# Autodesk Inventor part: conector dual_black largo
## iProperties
Created: 2008-01
Part Number: conector dual_black largo
Document SubType Name: Modeling
Designer: eruiz-tagle
Mass: 0.0867993 g
Surface Area: 6.41708 cm^2
Volume: 0.0867993 cm^3
Density: 1 g/cm^3
Author: eruiz-tagle
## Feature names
1. Extrusion1
2. Shell1
3. Revolution1
4. Extrusion2
5. Fillet1
6. Rectangular Pattern1
7. Rectangular Pattern2
8. Mirror1
9. Mirror2
10. Revolution2
11. Mirror3
12. Extrusion3
13. Extrusion4
14. Fillet2
15. Fillet3
16. Mirror4
17. Fillet4
18. Fillet5
